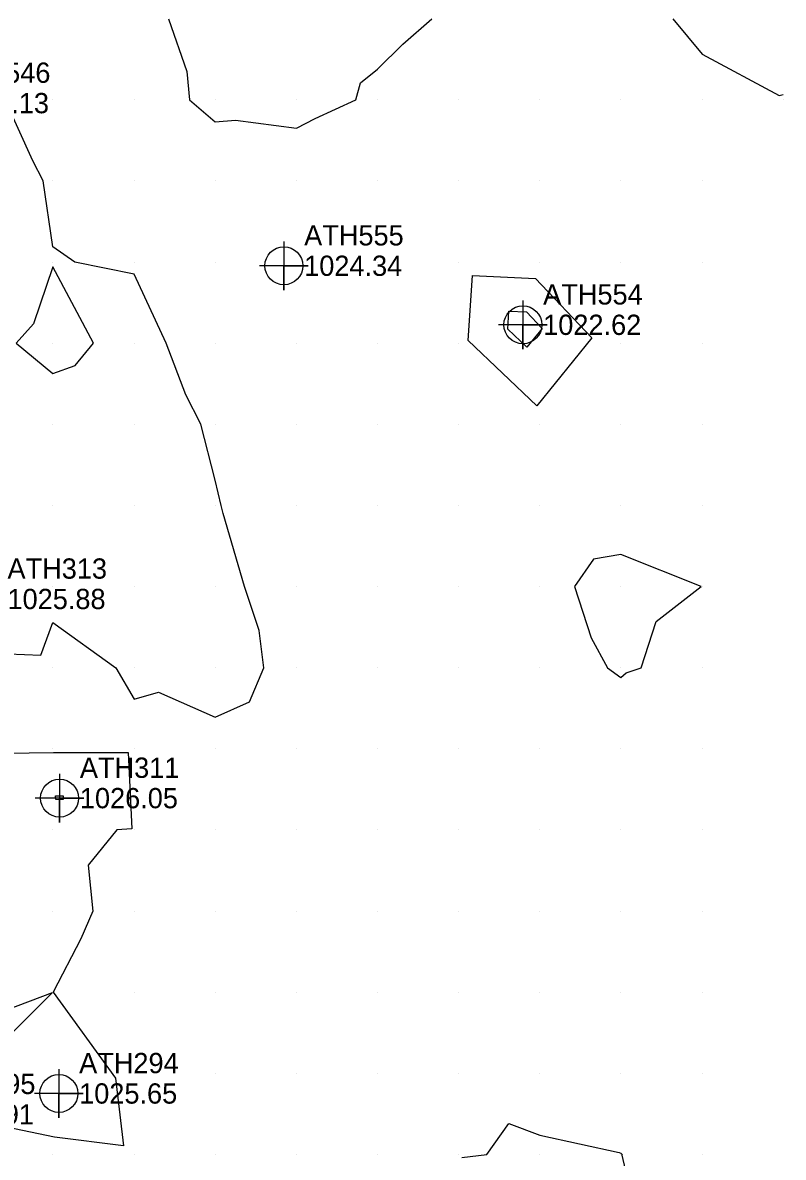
# Model space of a CAD drawing. Extents: x 1213164 to 1213550, y 766120 to 766870.
# Drawn here: x 1213406.3 to 1213500, y 766399.6 to 766539.5 of the extents above; entities that cross this region are included whole.
import ezdxf

# ---------------------------------------------------------------- set-up
doc = ezdxf.new("R2010")
doc.units = 0
for name, color, linetype in [('Default', 7, 'Continuous'), ('Exist DTM Breakline Cogo Elevation', 7, 'Continuous'), ('Exist DTM Breakline Cogo Number', 7, 'Continuous'), ('Exist DTM QL2 LIDAR Elevation Point', 7, 'Continuous'), ('Exist DTM Regular Point CELL', 7, 'Continuous'), ('Exist DTM Regular Point Cogo Elevation', 7, 'Continuous'), ('Exist DTM Regular Point Cogo Number', 7, 'Continuous')]:
    doc.layers.add(name, color=color, linetype=linetype)

msp = doc.modelspace()

# ---------------------------------------------------------------- linework, layer by layer
at = {"layer": 'Default'}
for points in [[(1213424.23, 766540), (1213426.51, 766533.49), (1213426.84, 766530), (1213430, 766527.3), (1213432.49, 766527.51), (1213440, 766526.5), (1213442.31, 766527.69), (1213447.33, 766530), (1213447.92, 766532.08), (1213450, 766533.79), (1213453.12, 766536.88), (1213456.69, 766540)], [(1213486.39, 766540), (1213490, 766535.63), (1213499.48, 766530.52), (1213500, 766530.67)], [(1213400.42, 766461.89), (1213408.51, 766461.56), (1213410, 766465.58), (1213417.77, 766460), (1213420, 766456.12), (1213423.01, 766456.99), (1213430, 766453.91), (1213434.23, 766455.77), (1213435.97, 766460), (1213435.43, 766464.57), (1213433.61, 766470), (1213430.98, 766479.02), (1213430.72, 766480), (1213430, 766483.1), (1213428.22, 766490), (1213426.37, 766493.63), (1213423.96, 766500), (1213420, 766508.53), (1213412.7, 766510), (1213410, 766511.89), (1213408.8, 766520), (1213407.52, 766522.48), (1213404.11, 766530)], [(1213410, 766509.4), (1213407.62, 766502.38), (1213405.48, 766500), (1213410, 766496.26), (1213412.76, 766497.24), (1213415.01, 766500), (1213410, 766509.4)], [(1213461.18, 766500.34), (1213461.69, 766508.34), (1213469.45, 766507.97), (1213476.42, 766500.67), (1213469.61, 766492.28), (1213461.18, 766500.34)], [(1213466.04, 766501.73), (1213466.18, 766503.96), (1213468.34, 766503.86), (1213470.28, 766501.83), (1213468.38, 766499.5), (1213466.04, 766501.73)], [(1213489.87, 766470), (1213480, 766473.96), (1213476.61, 766473.39), (1213474.27, 766470), (1213476.32, 766463.68), (1213478.34, 766460), (1213480, 766458.78), (1213480.64, 766459.36), (1213482.48, 766460), (1213484.32, 766465.68), (1213489.87, 766470)], [(1213401.04, 766449.42), (1213410.06, 766449.56), (1213419.28, 766449.53), (1213419.73, 766440.12), (1213417.87, 766440), (1213414.36, 766435.64), (1213414.9, 766430), (1213413.42, 766426.58), (1213410.02, 766420), (1213410.02, 766419.98), (1213417.72, 766409.39), (1213418.71, 766401.04), (1213410.21, 766402.14), (1213395.16, 766405.24), (1213409.9, 766419.91), (1213392.6, 766413.4)], [(1213410.35, 766443.75), (1213410.32, 766444.2), (1213410.78, 766444.21), (1213411.26, 766444.21), (1213411.28, 766443.73), (1213410.78, 766443.7), (1213410.35, 766443.75)], [(1213460.37, 766399.63), (1213463.48, 766400), (1213466.18, 766403.82), (1213470, 766402.36), (1213479.77, 766400.23), (1213480, 766400.14), (1213480.15, 766400), (1213480.11, 766399.89), (1213482.42, 766390)]]:
    msp.add_lwpolyline(points, dxfattribs=at)
at = {"layer": 'Exist DTM QL2 LIDAR Elevation Point'}
for p, q in [((1213410, 766530), (1213410, 766530)), ((1213420, 766530), (1213420, 766530)), ((1213430, 766530), (1213430, 766530)), ((1213440, 766530), (1213440, 766530)), ((1213450, 766530), (1213450, 766530)), ((1213460, 766530), (1213460, 766530)), ((1213470, 766530), (1213470, 766530)), ((1213480, 766530), (1213480, 766530)), ((1213490, 766530), (1213490, 766530)), ((1213500, 766530), (1213500, 766530)), ((1213410, 766520), (1213410, 766520)), ((1213420, 766520), (1213420, 766520)), ((1213430, 766520), (1213430, 766520)), ((1213440, 766520), (1213440, 766520)), ((1213450, 766520), (1213450, 766520)), ((1213460, 766520), (1213460, 766520)), ((1213470, 766520), (1213470, 766520)), ((1213480, 766520), (1213480, 766520)), ((1213490, 766520), (1213490, 766520)), ((1213410, 766510), (1213410, 766510)), ((1213420, 766510), (1213420, 766510)), ((1213430, 766510), (1213430, 766510)), ((1213450, 766510), (1213450, 766510)), ((1213460, 766510), (1213460, 766510)), ((1213470, 766510), (1213470, 766510)), ((1213480, 766510), (1213480, 766510)), ((1213490, 766510), (1213490, 766510)), ((1213410, 766500), (1213410, 766500)), ((1213420, 766500), (1213420, 766500)), ((1213430, 766500), (1213430, 766500)), ((1213440, 766500), (1213440, 766500)), ((1213450, 766500), (1213450, 766500)), ((1213460, 766500), (1213460, 766500)), ((1213480, 766500), (1213480, 766500)), ((1213490, 766500), (1213490, 766500)), ((1213410, 766490), (1213410, 766490)), ((1213420, 766490), (1213420, 766490)), ((1213430, 766490), (1213430, 766490)), ((1213440, 766490), (1213440, 766490)), ((1213450, 766490), (1213450, 766490)), ((1213460, 766490), (1213460, 766490)), ((1213470, 766490), (1213470, 766490)), ((1213480, 766490), (1213480, 766490)), ((1213490, 766490), (1213490, 766490)), ((1213410, 766480), (1213410, 766480)), ((1213420, 766480), (1213420, 766480)), ((1213430, 766480), (1213430, 766480)), ((1213440, 766480), (1213440, 766480)), ((1213450, 766480), (1213450, 766480)), ((1213460, 766480), (1213460, 766480)), ((1213470, 766480), (1213470, 766480)), ((1213480, 766480), (1213480, 766480)), ((1213490, 766480), (1213490, 766480)), ((1213410, 766470), (1213410, 766470)), ((1213420, 766470), (1213420, 766470)), ((1213430, 766470), (1213430, 766470)), ((1213440, 766470), (1213440, 766470)), ((1213450, 766470), (1213450, 766470)), ((1213460, 766470), (1213460, 766470)), ((1213470, 766470), (1213470, 766470)), ((1213480, 766470), (1213480, 766470)), ((1213490, 766470), (1213490, 766470)), ((1213410, 766460), (1213410, 766460)), ((1213420, 766460), (1213420, 766460)), ((1213430, 766460), (1213430, 766460)), ((1213440, 766460), (1213440, 766460)), ((1213450, 766460), (1213450, 766460)), ((1213460, 766460), (1213460, 766460)), ((1213470, 766460), (1213470, 766460)), ((1213480, 766460), (1213480, 766460)), ((1213490, 766460), (1213490, 766460)), ((1213410, 766450), (1213410, 766450)), ((1213420, 766450), (1213420, 766450)), ((1213430, 766450), (1213430, 766450)), ((1213440, 766450), (1213440, 766450)), ((1213450, 766450), (1213450, 766450)), ((1213460, 766450), (1213460, 766450)), ((1213470, 766450), (1213470, 766450)), ((1213480, 766450), (1213480, 766450)), ((1213490, 766450), (1213490, 766450)), ((1213410, 766440), (1213410, 766440)), ((1213420, 766440), (1213420, 766440)), ((1213430, 766440), (1213430, 766440)), ((1213440, 766440), (1213440, 766440)), ((1213450, 766440), (1213450, 766440)), ((1213460, 766440), (1213460, 766440)), ((1213470, 766440), (1213470, 766440)), ((1213480, 766440), (1213480, 766440)), ((1213490, 766440), (1213490, 766440)), ((1213410, 766430), (1213410, 766430)), ((1213420, 766430), (1213420, 766430)), ((1213430, 766430), (1213430, 766430)), ((1213440, 766430), (1213440, 766430)), ((1213450, 766430), (1213450, 766430)), ((1213460, 766430), (1213460, 766430)), ((1213470, 766430), (1213470, 766430)), ((1213480, 766430), (1213480, 766430)), ((1213490, 766430), (1213490, 766430)), ((1213410, 766420), (1213410, 766420)), ((1213420, 766420), (1213420, 766420)), ((1213430, 766420), (1213430, 766420)), ((1213440, 766420), (1213440, 766420)), ((1213450, 766420), (1213450, 766420)), ((1213460, 766420), (1213460, 766420)), ((1213470, 766420), (1213470, 766420)), ((1213480, 766420), (1213480, 766420)), ((1213490, 766420), (1213490, 766420)), ((1213420, 766410), (1213420, 766410)), ((1213430, 766410), (1213430, 766410)), ((1213440, 766410), (1213440, 766410)), ((1213450, 766410), (1213450, 766410)), ((1213460, 766410), (1213460, 766410)), ((1213470, 766410), (1213470, 766410)), ((1213480, 766410), (1213480, 766410)), ((1213490, 766410), (1213490, 766410)), ((1213410, 766400), (1213410, 766400)), ((1213420, 766400), (1213420, 766400)), ((1213430, 766400), (1213430, 766400)), ((1213440, 766400), (1213440, 766400)), ((1213450, 766400), (1213450, 766400)), ((1213460, 766400), (1213460, 766400)), ((1213470, 766400), (1213470, 766400)), ((1213480, 766400), (1213480, 766400)), ((1213490, 766400), (1213490, 766400))]:
    msp.add_line(p, q, dxfattribs=at)
at = {"layer": 'Exist DTM Regular Point CELL'}
for points in [[(1213438.46, 766512.55), (1213438.46, 766506.55), (1213438.46, 766509.55), (1213441.46, 766509.55), (1213435.46, 766509.55)], [(1213467.91, 766505.27), (1213467.91, 766499.27), (1213467.91, 766502.27), (1213470.91, 766502.27), (1213464.91, 766502.27)], [(1213410.82, 766446.92), (1213410.82, 766440.92), (1213410.82, 766443.92), (1213413.82, 766443.92), (1213407.82, 766443.92)], [(1213410.73, 766410.51), (1213410.73, 766404.51), (1213410.73, 766407.51), (1213413.73, 766407.51), (1213407.73, 766407.51)]]:
    msp.add_lwpolyline(points, dxfattribs=at)
for centre in [(1213438.46, 766509.55), (1213467.91, 766502.27), (1213410.82, 766443.92), (1213410.73, 766407.51)]:
    msp.add_circle(centre, 2.34, dxfattribs=at)

# ---------------------------------------------------------------- texts
at = {"layer": 'Exist DTM Breakline Cogo Elevation'}
msp.add_text('1024.91', height=2.5, dxfattribs=at).set_placement((1213395.58, 766403.69))
at = {"layer": 'Exist DTM Breakline Cogo Number'}
msp.add_text('ATH295', height=2.5, dxfattribs=at).set_placement((1213395.58, 766407.44))
at = {"layer": 'Exist DTM Regular Point Cogo Elevation'}
for s, p in [('1025.13', (1213397.43, 766528.35)), ('1024.34', (1213440.96, 766508.3)), ('1022.62', (1213470.41, 766501.02)), ('1025.88', (1213404.4, 766467.22)), ('1026.05', (1213413.32, 766442.67)), ('1025.65', (1213413.23, 766406.26))]:
    msp.add_text(s, height=2.5, dxfattribs=at).set_placement(p)
at = {"layer": 'Exist DTM Regular Point Cogo Number'}
for s, p in [('ATH546', (1213397.43, 766532.1)), ('ATH555', (1213440.96, 766512.05)), ('ATH554', (1213470.41, 766504.77)), ('ATH313', (1213404.4, 766470.97)), ('ATH311', (1213413.32, 766446.42)), ('ATH294', (1213413.23, 766410.01))]:
    msp.add_text(s, height=2.5, dxfattribs=at).set_placement(p)

doc.saveas('drawing.dxf')
